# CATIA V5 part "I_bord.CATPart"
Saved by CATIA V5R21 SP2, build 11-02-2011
Part number: I_bord
Bounding box of the stored display mesh (mm): x -200 to 200, y -300 to 300, z 0 to 300
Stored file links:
  \\ariel.ad.iei.liu.se\LAB_DELMIA\A1_LAB_INTRO_2011\LAB_INTRO_DATA_2011\I_bord.CATPart
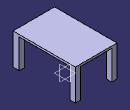
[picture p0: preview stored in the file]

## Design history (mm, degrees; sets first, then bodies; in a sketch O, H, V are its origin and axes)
Body1 (main body)
  Sketch1 on xy-plane, origin (0, 0, 0), H (1, 0, 0), V (0, 1, 0)
    line L1 (-200, -300) -> (200, -300)
    line L2 (200, -300) -> (200, 300)
    line L3 (200, 300) -> (-200, 300)
    line L4 (-200, 300) -> (-200, -300)
    horizontal: L1 H, L3 H
    vertical: L2 V, L4 V
  Pad1: profile Sketch1, direction (0, 0, 1), length 300
  Sketch2 on yz-plane, origin (0, 0, 0), H (0, 1, 0), V (0, 0, 1)
    point P1 (-240, 0)
    line L1 (-240, 0) -> (250, 0)
    line L2 (250, 0) -> (250, 280)
    line L3 (250, 280) -> (-240, 280)
    line L4 (-240, 280) -> (-240, 0)
    coincidence: P1 H
    horizontal: L1 H, L3 H
    vertical: L2 V, L4 V
  Pocket1: profile Sketch2, direction (-1, 0, 0), length 200, opposite side length 200
  Sketch3 on zx-plane, origin (0, 0, 0), H (-1, 0, 0), V (0, 0, 1)
    point P1 (-150, 0)
    line L1 (-150, 0) -> (150, 0)
    line L2 (150, 0) -> (150, 280)
    line L3 (150, 280) -> (-150, 280)
    line L4 (-150, 280) -> (-150, 0)
    coincidence: P1 H
    horizontal: L1 H, L3 H
    vertical: L2 V, L4 V
  Pocket2: profile Sketch3, direction (0, -1, 0), length 300, opposite side length 300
